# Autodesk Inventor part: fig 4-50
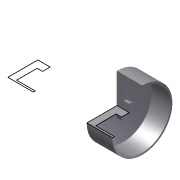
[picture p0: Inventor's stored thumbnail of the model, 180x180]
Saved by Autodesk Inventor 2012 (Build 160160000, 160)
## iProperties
Created: 2004-05
Part Number: fig 4-50
Document SubType Name: Modeling
Designer: CADCIM Technologies
Manufacturer: Standard
Standards Organization: Custom
Density: 1 g/cm^3
Material: Default
Author: CADCIM Technologies
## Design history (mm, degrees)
sketch "Sketch1"
  geometry: L1 (30.083, 49.92)-(16.646, 49.92); L2 (16.646, 49.92)-(16.646, 17.104); L3 (16.646, 17.104)-(44.553, 17.104); L4 (44.553, 17.104)-(44.553, 19.171); L5 (44.553, 19.171)-(24.139, 19.171); L6 (24.139, 19.171)-(24.139, 41.652); L7 (24.139, 41.652)-(30.083, 41.652); L8 (30.083, 41.652)-(30.083, 49.92); L9 (116.437, 49.92)-(103, 49.92); L10 (103, 49.92)-(103, 17.104); L11 (103, 17.104)-(130.907, 17.104); L12 (130.907, 17.104)-(130.907, 19.171); L13 (130.907, 19.171)-(110.494, 19.171); L14 (110.494, 19.171)-(110.494, 41.652); L15 (110.494, 41.652)-(116.437, 41.652); L16 (116.437, 41.652)-(116.437, 49.92)
  constraints: 32 end point, 2 horizontal
revolve "Revolution1" sketch "Sketch1" stored, may be unused: angle "d0" = 270 deg
body "Solid1"
